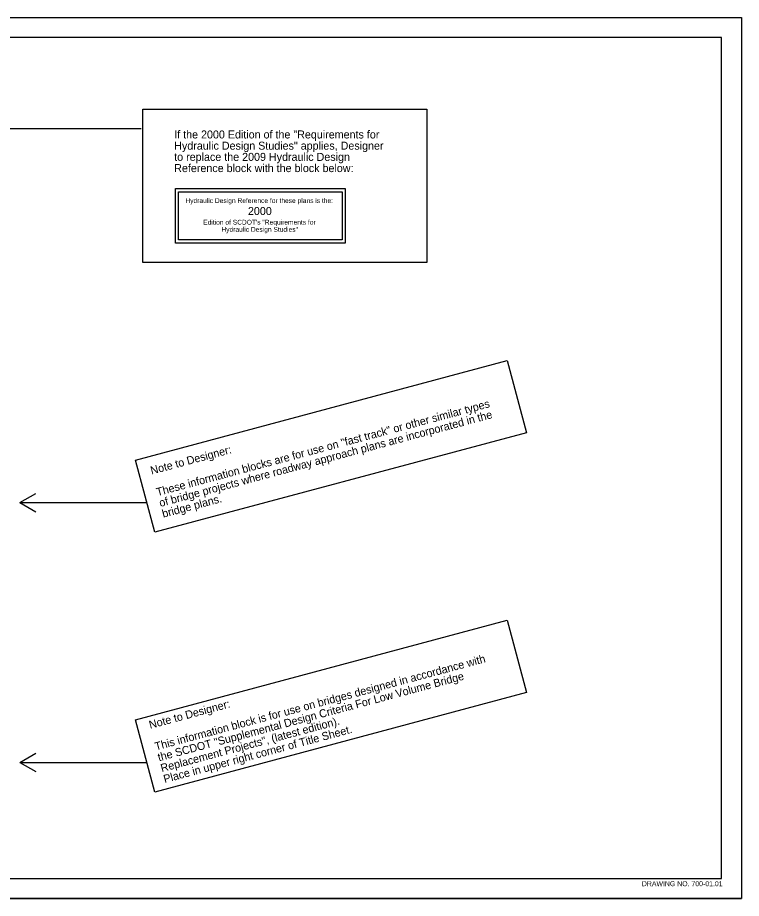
# Model space of a CAD drawing. Extents: x 841 to 4291, y -549 to 1701.
# Drawn here: x 3387 to 4291, y 601 to 1701 of the extents above; entities that cross this region are included whole.
import ezdxf

# ---------------------------------------------------------------- set-up
doc = ezdxf.new("R2010")
doc.units = 0
for name, color, linetype in [('BR_AUTO DIMENSION', 7, 'Continuous'), ('BR_BORDER LINES', 7, 'Continuous'), ('BR_DETAILS', 7, 'Continuous'), ('BR_TABLE LINES', 7, 'Continuous'), ('BR_TEXT', 7, 'Continuous'), ('RD_SHT_IplotShp', 7, 'Continuous')]:
    doc.layers.add(name, color=color, linetype=linetype)

msp = doc.modelspace()

# ---------------------------------------------------------------- linework, layer by layer
at = {"layer": 'BR_BORDER LINES'}
for p, q in [((2590.7, 1701.3), (4290.7, 1701.3)), ((4265.7, 1676.3), (2690.7, 1676.3)), ((4265.7, 626.3), (4265.7, 1676.3)), ((2690.7, 626.3), (4265.7, 626.3)), ((2590.7, 601.3), (4290.7, 601.3))]:
    msp.add_line(p, q, dxfattribs=at)
at = {"layer": 'BR_DETAILS'}
for points in [[(3796.4, 1419.8), (3584.4, 1419.8), (3584.4, 1487.8), (3796.4, 1487.8)], [(3792.4, 1423.8), (3588.4, 1423.8), (3588.4, 1483.8), (3792.4, 1483.8)]]:
    msp.add_lwpolyline(points, close=True, dxfattribs=at)
at = {"layer": 'BR_TABLE LINES'}
for p, q in [((3328.8, 1562.8), (3541.7, 1562.8)), ((3390.3, 1095.6), (3410.3, 1107.1)), ((3390.3, 1095.6), (3410.3, 1084)), ((3390.3, 1095.6), (3547.9, 1095.6)), ((3390.3, 771.1), (3410.3, 782.7)), ((3390.3, 771.1), (3410.3, 759.6)), ((3390.3, 771.1), (3547.9, 771.1))]:
    msp.add_line(p, q, dxfattribs=at)
for points in [[(3543.8, 1587.1), (3898.1, 1587.1), (3898.1, 1395.5), (3543.8, 1395.5)], [(3534.6, 1148.8), (3998.4, 1273), (4022.6, 1182.8), (3558.8, 1058.5)], [(3534.6, 824.3), (3998.4, 948.6), (4022.6, 858.4), (3558.8, 734.1)]]:
    msp.add_lwpolyline(points, close=True, dxfattribs=at)
at = {"layer": 'RD_SHT_IplotShp'}
msp.add_lwpolyline([(2590.7, 1701.3), (4290.7, 1701.3), (4290.7, 601.3), (2590.7, 601.3)], close=True, dxfattribs=at)

# ---------------------------------------------------------------- texts
at = {"layer": 'BR_AUTO DIMENSION'}
msp.add_text('DRAWING NO. 700-01.01', height=6.25, dxfattribs=at).set_placement((4166.5, 616.5))
at = {"layer": 'BR_DETAILS'}
for s, height, p in [('Hydraulic Design Reference for these plans is the:', 6, (3596.9, 1469.8)), ('2000', 10, (3674.9, 1454.8)), ('Edition of SCDOT\'s "Requirements for', 6, (3619.1, 1442.8)), ('Hydraulic Design Studies"', 6, (3641.8, 1433.8))]:
    msp.add_text(s, height=height, dxfattribs=at).set_placement(p)
at = {"layer": 'BR_TEXT'}
for s, rotation, p in [('If the 2000 Edition of the "Requirements for', 360, (3582.9, 1550.4)), ('Hydraulic Design Studies" applies, Designer ', 360, (3582.9, 1536.4)), ('to replace the 2009 Hydraulic Design ', 360, (3582.9, 1522.4)), ('Reference block with the block below:', 360, (3582.9, 1508.4)), ('These information blocks are for use on "fast track" or other similar types ', 15, (3562, 1103.6)), ('of bridge projects where roadway approach plans are incorporated in the', 15, (3565.6, 1090.1)), ('Note to Designer:', 15, (3554.7, 1130.6)), ('bridge plans.', 15, (3569.2, 1076.6)), ('This information block is for use on bridges designed in accordance with', 15, (3560.1, 785.9)), ('the SCDOT "Supplemental Design Criteria For Low Volume Bridge', 15, (3563.8, 772.4)), ('Note to Designer:', 15, (3552.9, 813)), ('Replacement Projects", (latest edition).', 15, (3567.4, 758.9)), ('Place in upper right corner of Title Sheet.', 15, (3571, 745.3))]:
    msp.add_text(s, height=10, rotation=rotation, dxfattribs=at).set_placement(p)

doc.saveas('drawing.dxf')
